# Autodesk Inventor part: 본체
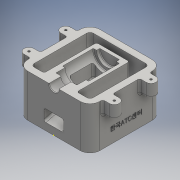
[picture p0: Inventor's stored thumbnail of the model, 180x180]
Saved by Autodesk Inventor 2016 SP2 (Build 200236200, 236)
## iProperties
Created: 2018-01
Part Number: 본체
Material: Generic
Document SubType Name: Modeling
Designer: Administrator
Density: 1 g/cm^3
Appearance: Default
Author: Administrator
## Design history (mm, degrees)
sketch "스케치1"
  geometry: L1 (55, -55)-(-55, -55); L2 (-55, -55)-(-55, 55); L3 (-55, 55)-(55, 55); L4 (55, 55)-(55, -55); L5 (55, -55)-(-55, 55); L6 (-55, -55)-(55, 55); 1 further point
  constraints: 12 end point, 2 midpoint, 2 parallel, 1 horizontal, 1 perpendicular
  dimensions: "d0" = 110 distance between parallel lines of L1 L3; "d1" = 110 distance between parallel lines of L4 L2
extrude "돌출1" new body sketch "스케치1" distance "d2" = 65; taper "d3" = 0 deg
sketch "스케치2"
  geometry: L1 (-55, -55)-(55, -55) reference; L2 (-55, 55)-(-55, -55) reference; L3 (55, -55)-(55, 55) reference; L4 (-65, -35.5)-(-55, -35.5); L5 (-65, -20.5)-(-55, -20.5); L6 (-65, 20.5)-(-55, 20.5); L7 (-65, 35.5)-(-55, 35.5); L8 (55, -35.5)-(65, -35.5); L9 (55, -20.5)-(65, -20.5); L10 (55, 20.5)-(65, 20.5); L11 (55, 35.5)-(65, 35.5); A1 r 7.5 centre (-65, -28) between (-65, -20.5) and (-65, -35.5); A2 r 7.5 centre (-65, 28) between (-65, 35.5) and (-65, 20.5); A3 r 7.5 centre (65, -28) between (65, -35.5) and (65, -20.5); A4 r 7.5 centre (65, 28) between (65, 20.5) and (65, 35.5); 1 further point
  constraints: 16 end point, 8 horizontal, 8 point on circle, 8 point on line, 8 tangent, 4 centre point, 2 horizontal alignment, 2 vertical alignment
  dimensions: "d4" = 15 diameter of A1; "d5" = 15 diameter of A2; "d6" = 27 distance from line of A1.centre L1; "d7" = 56 distance of A2.centre A1.centre; "d8" = 10 distance from line of L2 A1.centre; "d9" = 15 diameter of A3; "d10" = 15 diameter of A4; "d11" = 10 distance from line of A3.centre L3
extrude "돌출2" join sketch "스케치2" distance "d12" = 20; taper "d13" = 0 deg
sketch "스케치3"
  geometry: L1 (-55, -55)-(55, -55) reference; L2 (55, -55)-(55, -35.5) reference; L3 (55, -35.5)-(65, -35.5) reference; L4 (65, -20.5)-(55, -20.5) reference; L5 (55, -20.5)-(55, 20.5) reference; L6 (55, 20.5)-(65, 20.5) reference; L7 (65, 35.5)-(55, 35.5) reference; L8 (55, 35.5)-(55, 55) reference; L9 (55, 55)-(-55, 55) reference; L10 (-55, 55)-(-55, 35.5) reference; L11 (-55, 35.5)-(-65, 35.5) reference; L12 (-65, 20.5)-(-55, 20.5) reference; L13 (-55, 20.5)-(-55, -20.5) reference; L14 (-55, -20.5)-(-65, -20.5) reference; L15 (-65, -35.5)-(-55, -35.5) reference; L16 (-55, -35.5)-(-55, -55) reference; A1 r 7.5 centre (-65, 28) between (-65, 35.5) and (-65, 20.5) reference; A2 r 7.5 centre (65, 28) between (65, 20.5) and (65, 35.5) reference; A3 r 7.5 centre (65, -28) between (65, -35.5) and (65, -20.5) reference; A4 r 7.5 centre (65, -28) between (65, -35.5) and (65, -20.5) reference; A5 r 7.5 centre (65, 28) between (65, 20.5) and (65, 35.5) reference; A6 r 7.5 centre (-65, 28) between (-65, 35.5) and (-65, 20.5) reference; A7 r 7.5 centre (-65, -28) between (-65, -20.5) and (-65, -35.5) reference; A8 r 7.5 centre (-65, -28) between (-65, -20.5) and (-65, -35.5) reference; 5 further points
  constraints: 4 coincident
hole "구멍1" sketch "스케치3" at (-65, 28), (-65, -28), (65, 28), (65, -28) diameter "d14" = 3.242; stored, may be unused: countersink angle "d18" = 90 deg, drill point angle "d20" = 118 deg; dims "d15" = 9, "d16" = 4, "d17" = 2, "d19" = 11
sketch "스케치4"
  geometry: L1 (-55, 20.5)-(-55, -20.5) reference; L2 (55, -20.5)-(55, 20.5) reference; L3 (55, 55)-(-55, 55) reference; L4 (-25, -55.439)-(-25, 35); L5 (-25, 35)-(25, 35); L6 (25, 35)-(25, -55); L7 (-55, -55)-(55, -55) reference; L8 (-25, -45)-(-45, -45); L9 (-45, -45)-(-45, 45); L10 (-45, 45)-(45, 45); L11 (45, 45)-(45, -45); L12 (45, -45)-(25, -45); 1 further point
  constraints: 16 end point, 5 point on line, 4 perpendicular, 1 horizontal, 1 parallel, 1 vertical
  dimensions: "d26" = 30 distance between parallel lines of L4 L1; "d27" = 30 distance between parallel lines of L2 L6; "d28" = 20 distance between parallel lines of L3 L5; "d29" = 10 distance between parallel lines of L7 L8; "d30" = 10 distance between parallel lines of L1 L9; "d31" = 10 distance between parallel lines of L10 L3; "d32" = 10 distance between parallel lines of L2 L11
extrude "돌출3" cut sketch "스케치4" distance "d33" = 65; taper "d34" = 0 deg
sketch "스케치7"
  geometry: 1 further point
sketch "스케치8"
  geometry: L1 (-35.5, 65)-(-55, 65) reference; L2 (55, 65)-(35.5, 65) reference; L3 (-55, 65)-(55, 65); L4 (-55, 65)-(-55, 72.5); L5 (-55, 72.5)-(-36, 72.5); L6 (-36, 72.5)-(-36, 81); L7 (-36, 81)-(-22, 81); L8 (-22, 81)-(-22, 85); L9 (-22, 85)-(25, 85); L10 (25, 85)-(25, 80); L11 (25, 80)-(30, 80); L12 (30, 80)-(30, 65); L13 (-45, 65)-(45, 65) reference; 1 further point
  constraints: 20 end point, 7 perpendicular, 2 vertical, 1 horizontal, 1 point on line
  dimensions: "d37" = 15 diameter of L5 L3; "d38" = 19 distance between parallel lines of L6 L4; "d39" = 32 diameter of L7 L3; "d40" = 14 distance between parallel lines of L8 L6; "d41" = 40 diameter of L9 L3; "d42" = 47 distance between parallel lines of L10 L8; "d43" = 30 diameter of L11 L3; "d44" = 5 distance between parallel lines of L12 L10
revolve "회전1" sketch "스케치8" stored, may be unused: angle "d45" = 90 deg
sketch "스케치10"
  geometry: L1 (-17, 39.243)-(-55, 29.061); L2 (-22, 65)-(25, 65) reference; L3 (-55, 0)-(-55, 65) reference; L4 (20, 31.157)-(-55, 11.061); L5 (35, 65)-(35, 0) reference; L6 (35, 30)-(-35.681, 11.061); L7 (-45, 0)-(35, 0) reference; L8 (-17, 53)-(-17, 39.243); L9 (20, 53)-(20, 31.157); L10 (20, 53)-(-17, 53); L11 (-35.681, 11.061)-(-35.681, 0); L12 (25, 65)-(25, 50) reference; L13 (-22, 65)-(-22, 49) reference; 1 further point
  constraints: 14 end point, 4 point on line, 2 parallel, 2 vertical, 1 horizontal, 1 horizontal alignment, 1 perpendicular
  dimensions: "d53" = 75 deg angle of L1 L3; "d54" = 30 distance from line of L7 L6.start; "d55" = 5 distance between parallel lines of L6 L4; "d56" = 18 distance of L4.end L1.end; "d57" = 37 distance between parallel lines of L9 L8; "d58" = 12 distance between parallel lines of L10 L2; "d90" = 5 distance between parallel lines of L12 L9; "d91" = 5 distance between parallel lines of L8 L13 (derived)
extrude "돌출5" cut sketch "스케치10" stored distance "d59" = 30; taper "d60" = 0 deg
sketch "스케치11"
  geometry: L1 (0, 110)-(0, 0) reference; L2 (0, 0)-(-65, 0) reference; 3 further points
  constraints: 1 coincident, 1 other
  dimensions: "d62" = 20 distance from line of L1 point (-20, 55); "d63" = 55 distance from line of point (-20, 55) L2
feature "엠보싱1" sketch "스케치11" dims "d0" = 110, "d1" = 110, "d4" = 15, "d5" = 15, "d6" = 27, "d7" = 56, "d8" = 10, "d9" = 15, "d10" = 15, "d11" = 10, "d64" = 0.5, "d65" = 0
sketch "스케치14"
  geometry: L1 (20, 31.157)-(-55, 11.061) reference; L2 (35, 65)-(35, 0) reference; L3 (35, 30)-(-45, 8.564); L4 (35, 30)-(35, 0); L5 (-55, 0)-(55, 0) reference; L6 (-45, 8.564)-(-45, 0); L7 (-55, 0)-(-55, 65) reference; 1 further point
  constraints: 6 end point, 2 point on line, 1 collinear, 1 parallel, 1 perpendicular
  dimensions: "d75" = 10 distance between parallel lines of L6 L7; "d76" = 5 distance between parallel lines of L3 L1
extrude "돌출7" cut sketch "스케치14" stored distance "d73" = 50; taper "d74" = 0 deg
fillet "모깎기1" dims "d77" = 5
fillet "모깎기3" dims "d79" = 1
fillet "모깎기5" dims "d81" = 3
fillet "모깎기7" dims "d83" = 3
fillet "모깎기9" dims "d85" = 15
fillet "모깎기13" dims "d89" = 3
fillet "모깎기14" dims "d95" = 3
fillet "모깎기15" dims "d96" = 3
fillet "모깎기16" dims "d97" = 3
fillet "모깎기18" dims "d99" = 3
fillet "모깎기22" dims "d103" = 3
fillet "모깎기23" dims "d104" = 3
node "솔리드1"
node "투영된 루프1"
other parameters: "d51" = 37
